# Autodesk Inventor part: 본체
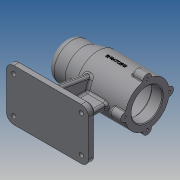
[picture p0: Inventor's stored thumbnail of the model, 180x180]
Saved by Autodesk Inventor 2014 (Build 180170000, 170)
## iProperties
Created: 2019-07
Part Number: 본체
Material: Generic
Document SubType Name: Modeling
Designer: kb542-7
Density: 1 g/cm^3
Appearance: Default
Author: kb542-7
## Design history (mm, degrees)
sketch "스케치1"
  geometry: L1 (-56, 0)-(-56, 25); L2 (-56, 25)-(-31, 25); L3 (-31, 25)-(-11, 30); L4 (-11, 30)-(56, 30); L5 (56, 30)-(56, 21); L6 (56, 0)-(-56, 0); L7 (-50, 0)-(-50, 10.5); L8 (-50, 10.5)-(-47, 10.5); L9 (-47, 10.5)-(-47, 16); L10 (-47, 16)-(-43, 16); L11 (-43, 16)-(-43, 17.5); L12 (-43, 17.5)-(-25, 17.5); L13 (-25, 17.5)-(-25, 21); L14 (-25, 21)-(-13, 21); L15 (-13, 21)-(-13, 24); L16 (-13, 24)-(41, 24); L17 (41, 24)-(41, 21); L18 (41, 21)-(56, 21); 2 further points
  constraints: 36 end point, 10 parallel, 5 perpendicular, 1 coincident, 1 horizontal, 1 midpoint, 1 point on line, 1 vertical, 1 vertical alignment
  dimensions: "d0" = 25 distance from line of L2.end L1; "d1" = 45 distance from line of L1 L3.end; "d3" = 60 diameter of L4 L6; "d4" = 50 diameter of L2 L6; "d12" = 42 diameter of L18 L6; "d13" = 112 distance between parallel lines of L1 L5; "d14" = 48 diameter of L16 L6; "d15" = 54 distance of L15.end L16.end; "d16" = 15 distance of L17.end L5.end; "d17" = 42 diameter of L14 L6; "d18" = 35 diameter of L12 L6; "d19" = 32 diameter of L10 L6; "d20" = 21 diameter of L8 L6; "d21" = 3 distance of L7.end L8.end; "d22" = 4 distance of L9.end L10.end; "d23" = 18 distance of L11.end L12.end; "d24" = 12 distance of L13.end L14.end
revolve "회전1" sketch "스케치1" stored, may be unused: angle "d5" = 90 deg
sketch "스케치4"
  geometry: L1 (-56, -70)-(56, -70); L2 (56, -70)-(56, -80); L3 (56, -80)-(-56, -80); L4 (-56, -80)-(-56, -70); 2 further points
  constraints: 8 end point, 2 parallel, 1 horizontal, 1 midpoint, 1 perpendicular, 1 vertical alignment
  dimensions: "d25" = 112 distance of L2.end L3.end; "d26" = 10 distance of L1.end L2.end; "d27" = 80 distance from line of L3 point (0, 0)
extrude "돌출2" join sketch "스케치4" stored distance "d28" = 70; taper "d29" = 0 deg
sketch "스케치5"
  geometry: L1 (-70, -35)-(-70, 35) reference; L2 (-22.666, 19.654)-(-70, 28); L3 (-22.666, -19.654)-(-70, -28); L4 (-70, 35)-(-80, 35) reference; L5 (-80, -35)-(-70, -35) reference; A1 r 30 centre (0, 0) between (-22.666, 19.654) and (-22.666, -19.654) reference; 1 further point
  constraints: 4 end point, 2 point on circle, 2 point on line
  dimensions: "d30" = 7 distance from line of L2.end L4; "d31" = 7 distance from line of L5 L3.end; "d33" = 100 deg angle of L1 L3; "d34" = 100 deg angle of L1 L2
extrude "돌출3" join sketch "스케치5" stored distance "d35" = 8; taper "d36" = 0 deg
sketch "스케치7"
  geometry: L1 (-31, -25)-(-11, -30) reference; L2 (-11, -30)-(56, -30) reference; L3 (-56, -25)-(-31, -25) reference; L4 (-56, -70)-(56, -70) reference; L5 (-20.57, -27.607)-(-36, -70); L6 (31, -70)-(31, -30); L7 (56, -70)-(56, -80) reference; L8 (-56, -80)-(-56, -70) reference; 1 further point
  constraints: 4 end point, 4 point on line, 1 perpendicular
  dimensions: "d37" = 25 distance between parallel lines of L7 L6; "d38" = 110 deg angle of L4 L5; "d39" = 20 distance from line of L5.end L8
feature "리브1" dims "d40" = 1, "d41" = 8, "d42" = 0, "d43" = 0, "d44" = 1, "d45" = 1
feature "리브2" dims "d46" = 1, "d47" = 8, "d48" = 0, "d49" = 0, "d50" = 1, "d51" = 1
sketch "스케치8"
  geometry: C1 r 21 at (0, 0) reference; A1 r 6 centre (0, 30) between (5.97, 29.4) and (-5.97, 29.4); A2 r 30 centre (0, 0) between (4, -29.732) and (-4, -29.732) reference; A3 r 30 centre (0, 0) between (4, -29.732) and (-4, -29.732) reference; 1 further point
  constraints: 6 point on circle, 1 centre point, 1 coincident, 1 vertical alignment
  dimensions: "d55" = 6 radius of A1
extrude "돌출4" join sketch "스케치8" distance "d56" = 16; taper "d57" = 0 deg
sketch "스케치9"
  geometry: A1 r 6 centre (0, 0) between (5.97, -0.6) and (-5.97, -0.6) reference; 1 further point
  constraints: 1 coincident
hole "구멍1" sketch "스케치9" at (0, 0) diameter "d58" = 3.242; stored, may be unused: countersink angle "d62" = 90 deg, drill point angle "d64" = 118 deg; dims "d59" = 8, "d60" = 4, "d61" = 2, "d63" = 11
fillet "모깎기2" dims "d66" = 3
fillet "모깎기3" dims "d67" = 1
fillet "모깎기4" dims "d71" = 10
sketch "스케치11"
  geometry: C1 r 3 at (0, -10); C2 r 3 at (92, -10); C3 r 3 at (92, -60); C4 r 3 at (0, -60); A1 r 10 centre (92, -60) between (92, -70) and (102, -60) reference; A2 r 10 centre (92, -10) between (102, -10) and (92, 0) reference; A3 r 10 centre (0, -10) between (0, 0) and (-10, -10) reference; A4 r 10 centre (0, -60) between (-10, -60) and (0, -70) reference; 1 further point
  constraints: 4 centre point, 4 coincident, 3 equal radius
  dimensions: "d73" = 6 diameter of C1
extrude "돌출5" cut sketch "스케치11" stored distance "d74" = 16; taper "d75" = 0 deg
chamfer "모따기1" distance "d76" = 3; stored, may be unused: second distance "d77" = 2, angle "d78" = 45 deg
fillet "모깎기5" dims "d79" = 3
fillet "모깎기6" dims "d80" = 3
chamfer "모따기2" distance "d81" = 1; stored, may be unused: second distance "d82" = 2, angle "d83" = 45 deg
fillet "모깎기7" dims "d84" = 10
fillet "모깎기8" dims "d85" = 3
fillet "모깎기9" dims "d86" = 3
fillet "모깎기10" dims "d87" = 3
node "작업 평면1"
sketch "스케치12"
  geometry: L1 (56, 6.771)-(56, 29.226) reference; 2 further points
  constraints: 1 horizontal alignment, 1 other
  dimensions: "d89" = 42 distance from line of L1 point (14, 0)
feature "엠보싱1" sketch "스케치12" dims "d0" = 25, "d1" = 45, "d3" = 60, "d4" = 50, "d12" = 42, "d13" = 112, "d14" = 48, "d15" = 54, "d16" = 15, "d17" = 42, "d18" = 35, "d19" = 32, "d20" = 21, "d21" = 3, "d22" = 4, "d23" = 18, "d24" = 12, "d90" = 0.5, "d91" = 0
fillet "모깎기11" dims "d92" = 0.3
node "솔리드1"
pattern_circular "원형 패턴1" dims "d69" = 360 deg
